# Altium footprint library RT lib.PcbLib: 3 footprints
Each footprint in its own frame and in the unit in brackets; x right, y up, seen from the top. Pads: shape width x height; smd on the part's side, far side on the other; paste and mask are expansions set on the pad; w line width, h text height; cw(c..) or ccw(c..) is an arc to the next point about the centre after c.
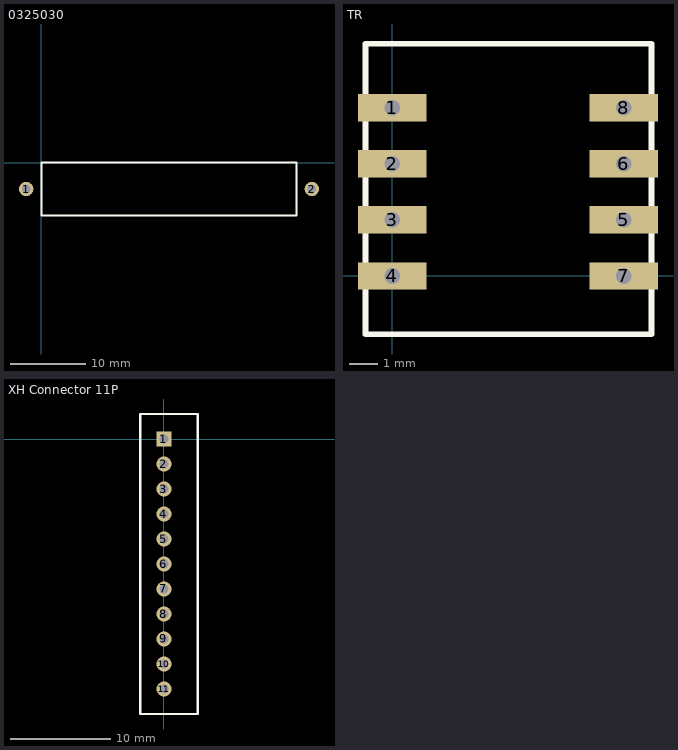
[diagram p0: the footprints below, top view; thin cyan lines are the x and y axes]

## 0325030 [mm]
pads (2):
  round 1.9 hole 1.15: 1(-2,-3.5) 2(35.8,-3.5)
Top Overlay:
  lines w0.254: 0,-7 33.7,-7 33.8,-7 33.8,0 0,0 0,-7

## TR [mm]
pads (8):
  rect 2.44x0.97 hole 0.56 square: 1(0,6) 2(0,4) 3(0,2) 4(0,0) 5(8.26,2) 6(8.26,4) 7(8.26,0) 8(8.26,6)
Top Overlay:
  lines w0.203: -0.95,-2.08 -0.95,8.28 9.25,8.28 9.25,-2.08 -0.95,-2.08
M5 Assembly Top:
  text ".Designator" at -1.8,-0.514 h1.02

## XH Connector 11P [mm]
pads (11):
  rect 1.5x1.5 hole 0.9: 1(0,0)
  round 1.5 hole 0.9: 2(0,-2.5) 3(0,-5) 4(0,-7.5) 5(0,-10) 6(0,-12.5) 7(0,-15) 8(0,-17.5) 9(0,-20) 10(0,-22.5) 11(0,-25)
Top Overlay:
  lines w0.203: -2.375,-27.5 3.375,-27.5 3.375,2.5 -2.375,2.5 -2.375,-27.5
